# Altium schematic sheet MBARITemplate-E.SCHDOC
size E; Organization: Monterey Bay Aquarium Research Institute; Address1: 7700 Sandholdt Rd; Address2: Moss Landing, CA 95039-9644; CompanyName: MBARI
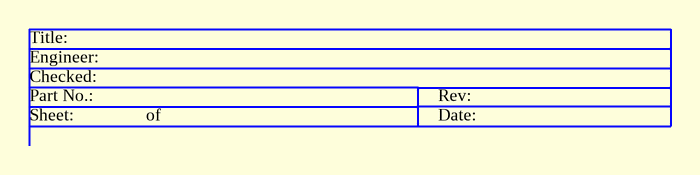
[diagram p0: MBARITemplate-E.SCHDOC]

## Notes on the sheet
- Title:
- Engineer:
- Sheet:
- Part No.:
- Checked:
- of
- Rev:
- Date:
